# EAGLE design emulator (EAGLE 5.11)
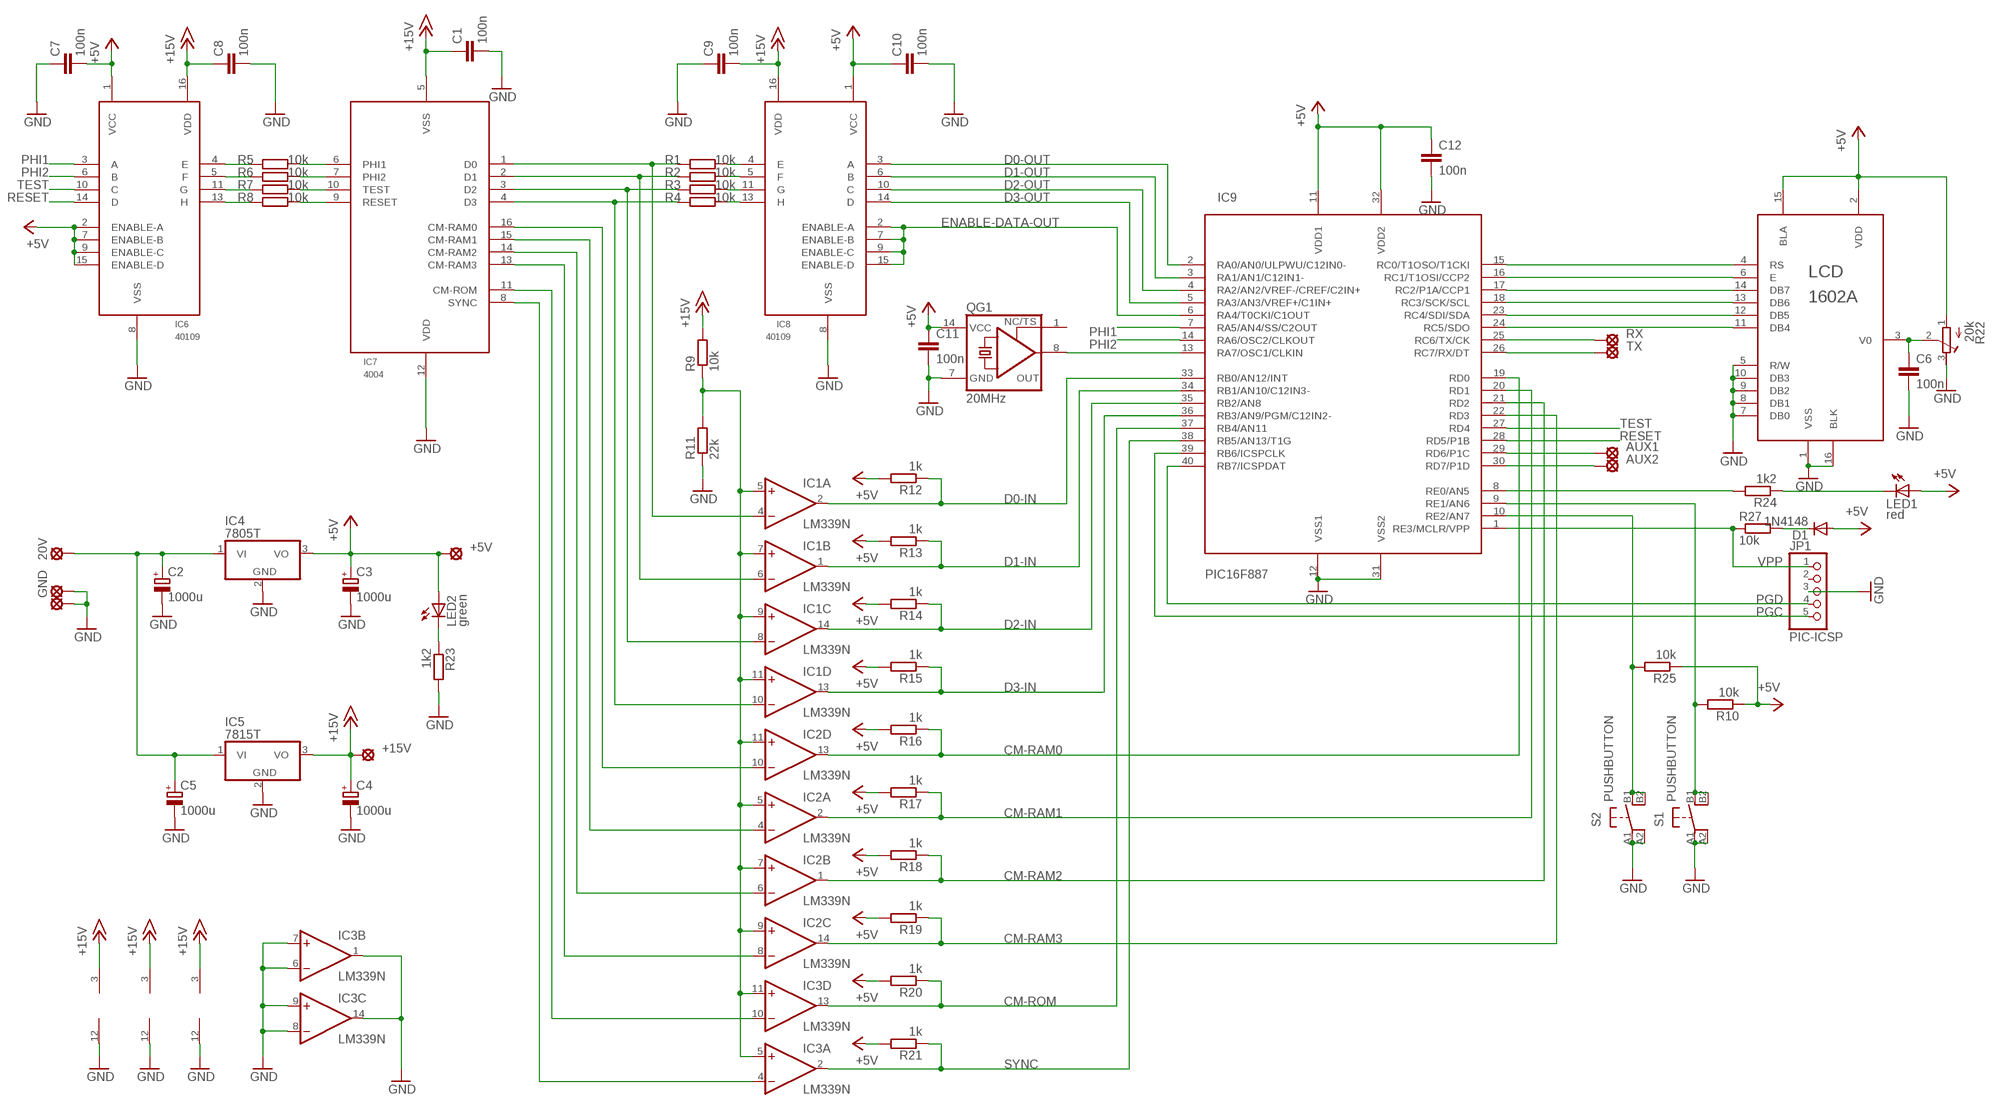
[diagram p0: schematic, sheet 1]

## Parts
20V  LSP10  [LSP10]
+5V  LSP10  [LSP10]
+15V  LSP10  [LSP10]
AUX1  LSP10  [LSP10]
AUX2  LSP10  [LSP10]
C1  100n  C-EU050-050X075  [C050-050X075]
C2  1000u  CPOL-EUE7.5-16  [E7,5-16]
C3  1000u  CPOL-EUE7.5-16  [E7,5-16]
C4  1000u  CPOL-EUE7.5-16  [E7,5-16]
C5  1000u  CPOL-EUE7.5-16  [E7,5-16]
C6  100n  C-EU050-050X075  [C050-050X075]
C7  100n  C-EU050-050X075  [C050-050X075]
C8  100n  C-EU050-050X075  [C050-050X075]
C9  100n  C-EU050-050X075  [C050-050X075]
C10  100n  C-EU050-050X075  [C050-050X075]
C11  100n  C-EU050-055X075  [C050-055X075]
C12  100n  C-EU050-050X075  [C050-050X075]
D1  1N4148  1N4148DO35-7  [DO35-7]
GND  LSP10  [LSP10]
GND29  LSP10  [LSP10]
IC1  LM339N  [DIL14]
IC2  LM339N  [DIL14]
IC3  LM339N  [DIL14]
IC4  7805T  [TO220H]
IC5  7815T  [TO220H]
IC6  40109  [DIL16]
IC7  4004  [DIL16/DIL40]
IC8  40109  [DIL16]
IC9  PIC16F887  [DIL40]
JP1  PIC-ICSP  PINHD-1X5  [1X05]
LCD  1602A  [1602A]
LED1  red  LED5MM  [LED5MM]
LED2  green  LED5MM  [LED5MM]
QG1  20MHz  XO-14  [DIL14S]
R1  10k  R-EU_0309/10  [0309/10]
R2  10k  R-EU_0309/10  [0309/10]
R3  10k  R-EU_0309/10  [0309/10]
R4  10k  R-EU_0309/10  [0309/10]
R5  10k  R-EU_0309/10  [0309/10]
R6  10k  R-EU_0309/10  [0309/10]
R7  10k  R-EU_0309/10  [0309/10]
R8  10k  R-EU_0309/10  [0309/10]
R9  10k  R-EU_0309/10  [0309/10]
R10  10k  R-EU_0309/10  [0309/10]
R11  22k  R-EU_0309/10  [0309/10]
R12  1k  R-EU_0309/10  [0309/10]
R13  1k  R-EU_0309/10  [0309/10]
R14  1k  R-EU_0309/10  [0309/10]
R15  1k  R-EU_0309/10  [0309/10]
R16  1k  R-EU_0309/10  [0309/10]
R17  1k  R-EU_0309/10  [0309/10]
R18  1k  R-EU_0309/10  [0309/10]
R19  1k  R-EU_0309/10  [0309/10]
R20  1k  R-EU_0309/10  [0309/10]
R21  1k  R-EU_0309/10  [0309/10]
R22  20k  R-TRIMM3339P  [RTRIM3339P]
R23  1k2  R-EU_0309/10  [0309/10]
R24  1k2  R-EU_0309/10  [0309/10]
R25  10k  R-EU_0309/10  [0309/10]
R27  10k  R-EU_0309/10  [0309/10]
RX  LSP10  [LSP10]
S1  PUSHBUTTON  [PUSHBUTTON]
S2  PUSHBUTTON  [PUSHBUTTON]
TX  LSP10  [LSP10]

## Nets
+5V: +5V.MP C3.+ C7.2 C10.1 C11.1 C12.1 D1.A IC4.3(VO) IC6.1(VCC) IC6.2(ENABLE-A) IC6.7(ENABLE-B) IC6.9(ENABLE-C) IC6.15(ENABLE-D) IC8.1(VCC) IC9.11(VDD1) IC9.32(VDD2) LCD.2(VDD) LCD.15(BLA) LED1.A LED2.A QG1.14(VCC) R10.1 R12.2 R13.2 R14.2 R15.2 R16.2 R17.2 R18.2 R19.2 R20.2 R21.2 R22.1(E) R25.1
+15V: +15V.MP C1.1 C4.+ C8.1 C9.2 IC1.3(P:V+) IC2.3(P:V+) IC3.3(P:V+) IC5.3(VO) IC6.16(VDD) IC7.5(VSS) IC8.16(VDD) R9.2
CM-RAM0: IC2.13(D:OUT) IC9.19(RD0) R16.1
CM-RAM1: IC2.2(A:OUT) IC9.20(RD1) R17.1
CM-RAM2: IC2.1(B:OUT) IC9.21(RD2) R18.1
CM-RAM3: IC2.14(C:OUT) IC9.22(RD3) R19.1
CM-ROM: IC3.13(D:OUT) IC9.37(RB4/AN11) R20.1
D0-IN: IC1.2(A:OUT) IC9.33(RB0/AN12/INT) R12.1
D0-OUT: IC8.3(A) IC9.2(RA0/AN0/ULPWU/C12IN0-)
D1-IN: IC1.1(B:OUT) IC9.34(RB1/AN10/C12IN3-) R13.1
D1-OUT: IC8.6(B) IC9.3(RA1/AN1/C12IN1-)
D2-IN: IC1.14(C:OUT) IC9.35(RB2/AN8) R14.1
D2-OUT: IC8.10(C) IC9.4(RA2/AN2/VREF-/CREF/C2IN+)
D3-IN: IC1.13(D:OUT) IC9.36(RB3/AN9/PGM/C12IN2-) R15.1
D3-OUT: IC8.14(D) IC9.5(RA3/AN3/VREF+/C1IN+)
ENABLE-DATA-OUT: IC8.2(ENABLE-A) IC8.7(ENABLE-B) IC8.9(ENABLE-C) IC8.15(ENABLE-D) IC9.6(RA4/T0CKI/C1OUT)
GND: C1.2 C2.- C3.- C4.- C5.- C6.2 C7.1 C8.2 C9.1 C10.2 C11.2 C12.2 GND29.MP GND.MP IC1.12(P:GND) IC2.12(P:GND) IC3.1(B:OUT) IC3.6(B:-IN) IC3.7(B:+IN) IC3.8(C:-IN) IC3.9(C:+IN) IC3.12(P:GND) IC3.14(C:OUT) IC4.2(GND) IC5.2(GND) IC6.8(VSS) IC7.12(VDD) IC8.8(VSS) IC9.12(VSS1) IC9.31(VSS2) JP1.3 LCD.1(VSS) LCD.5(R/W) LCD.7(DB0) LCD.8(DB1) LCD.9(DB2) LCD.10(DB3) LCD.16(BLK) QG1.7(GND) R11.1 R22.3(A) R23.2 S1.A1(P) S1.A2(P1) S2.A1(P) S2.A2(P1)
LCD-DB4: IC9.24(RC5/SDO) LCD.11(DB4)
LCD-DB5: IC9.23(RC4/SDI/SDA) LCD.12(DB5)
LCD-DB6: IC9.18(RC3/SCK/SCL) LCD.13(DB6)
LCD-DB7: IC9.17(RC2/P1A/CCP1) LCD.14(DB7)
LCD-E: IC9.16(RC1/T1OSI/CCP2) LCD.6(E)
LCD-RS: IC9.15(RC0/T1OSO/T1CKI) LCD.4(RS)
N$1: IC1.4(A:-IN) IC7.1(D0) R1.1
N$2: IC1.6(B:-IN) IC7.2(D1) R2.1
N$3: IC1.8(C:-IN) IC7.3(D2) R3.1
N$4: IC1.10(D:-IN) IC7.4(D3) R4.1
N$5: IC8.4(E) R1.2
N$6: IC8.5(F) R2.2
N$7: IC8.11(G) R3.2
N$8: IC8.13(H) R4.2
N$9: IC6.4(E) R5.1
N$10: IC6.5(F) R6.1
N$11: IC6.11(G) R7.1
N$12: IC6.13(H) R8.1
N$13: IC7.6(PHI1) R5.2
N$14: IC7.7(PHI2) R6.2
N$15: IC7.10(TEST) R7.2
N$16: IC7.9(RESET) R8.2
N$17: IC1.5(A:+IN) IC1.7(B:+IN) IC1.9(C:+IN) IC1.11(D:+IN) IC2.5(A:+IN) IC2.7(B:+IN) IC2.9(C:+IN) IC2.11(D:+IN) IC3.5(A:+IN) IC3.11(D:+IN) R9.1 R11.2
N$19: IC2.10(D:-IN) IC7.16(CM-RAM0)
N$20: IC2.4(A:-IN) IC7.15(CM-RAM1)
N$21: IC2.6(B:-IN) IC7.14(CM-RAM2)
N$22: IC2.8(C:-IN) IC7.13(CM-RAM3)
N$23: IC3.10(D:-IN) IC7.11(CM-ROM)
N$24: IC3.4(A:-IN) IC7.8(SYNC)
N$25: C6.1 LCD.3(V0) R22.2(S)
N$26: IC9.13(RA7/OSC1/CLKIN) QG1.8(OUT)
N$27: LED1.K(C) R24.1
N$28: 20V.MP C2.+ C5.+ IC4.1(VI) IC5.1(VI)
N$29: AUX1.MP IC9.29(RD6/P1C)
N$30: AUX2.MP IC9.30(RD7/P1D)
N$31: D1.C R27.2
N$32: IC9.9(RE1/AN6) R10.2 S1.B1(S) S1.B2(S1)
N$33: IC9.10(RE2/AN7) R25.2 S2.B1(S) S2.B2(S1)
N$34: LED2.K(C) R23.1
N$40: IC9.25(RC6/TX/CK) RX.MP
N$41: IC9.26(RC7/RX/DT) TX.MP
N$42: IC9.8(RE0/AN5) R24.2
PGC: IC9.39(RB6/ICSPCLK) JP1.5
PGD: IC9.40(RB7/ICSPDAT) JP1.4
PHI1: IC6.3(A) IC9.7(RA5/AN4/SS/C2OUT)
PHI2: IC6.6(B) IC9.14(RA6/OSC2/CLKOUT)
RESET: IC6.14(D) IC9.28(RD5/P1B)
SYNC: IC3.2(A:OUT) IC9.38(RB5/AN13/T1G) R21.1
TEST: IC6.10(C) IC9.27(RD4)
VPP: IC9.1(RE3/MCLR/VPP) JP1.1 R27.1
Unconnected: JP1.2 QG1.1(TS)

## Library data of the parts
20V +5V +15V AUX1 AUX2 GND GND29 RX TX = solpad:LSP10: SOLDER PAD
C1 C6-C12 = rcl:C-EU: CAPACITOR, European symbol
C2-C5 = rcl:CPOL-EU: POLARIZED CAPACITOR, European symbol
D1 = diode:1N4148: DIODE
IC1-IC3 = linear:LM339: Low Power Low Offset Voltage Quad Comparators with open collector; LM139/LM239/LM339/LM2901/LM3302
IC4 IC5 = linear:78*: Positive VOLTAGE REGULATOR Source: http://cache.national.com/ds/LM/LM78L05.pdf http://www.fairchildsemi.com/ds/LM/LM7805.pdf
IC6 IC8 = 4004:40109
IC7 = 4004:4004
IC9 = pic16f887:PIC16F887
JP1 = pinhead:PINHD-1X5: PIN HEADER
LCD = 1602A:1602A
LED1 LED2 = led:LED: LED
QG1 = crystal:XO-: CRYSTAL; OC_FARNELL: unknown; OC_NEWARK: unknown
R1-R21 R23-R25 R27 = rcl:R-EU_: RESISTOR, European symbol
R22 = rcl:R-TRIMM: Trimm resistor
S1 S2 = cartridge:PUSHBUTTON

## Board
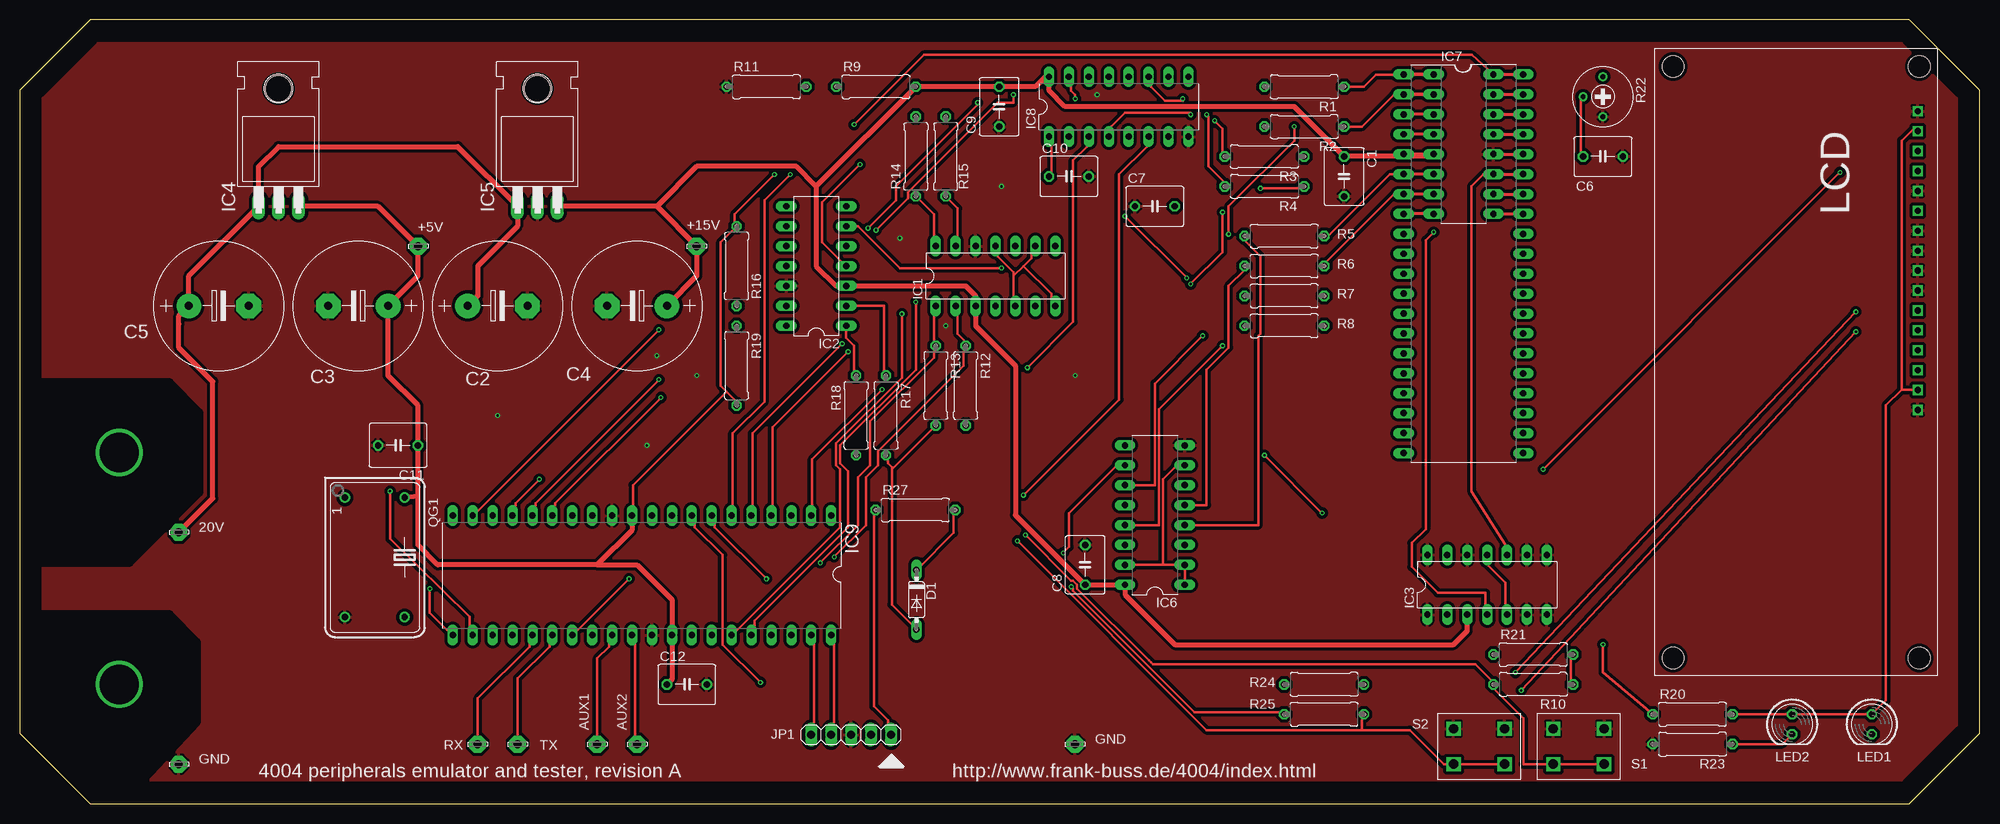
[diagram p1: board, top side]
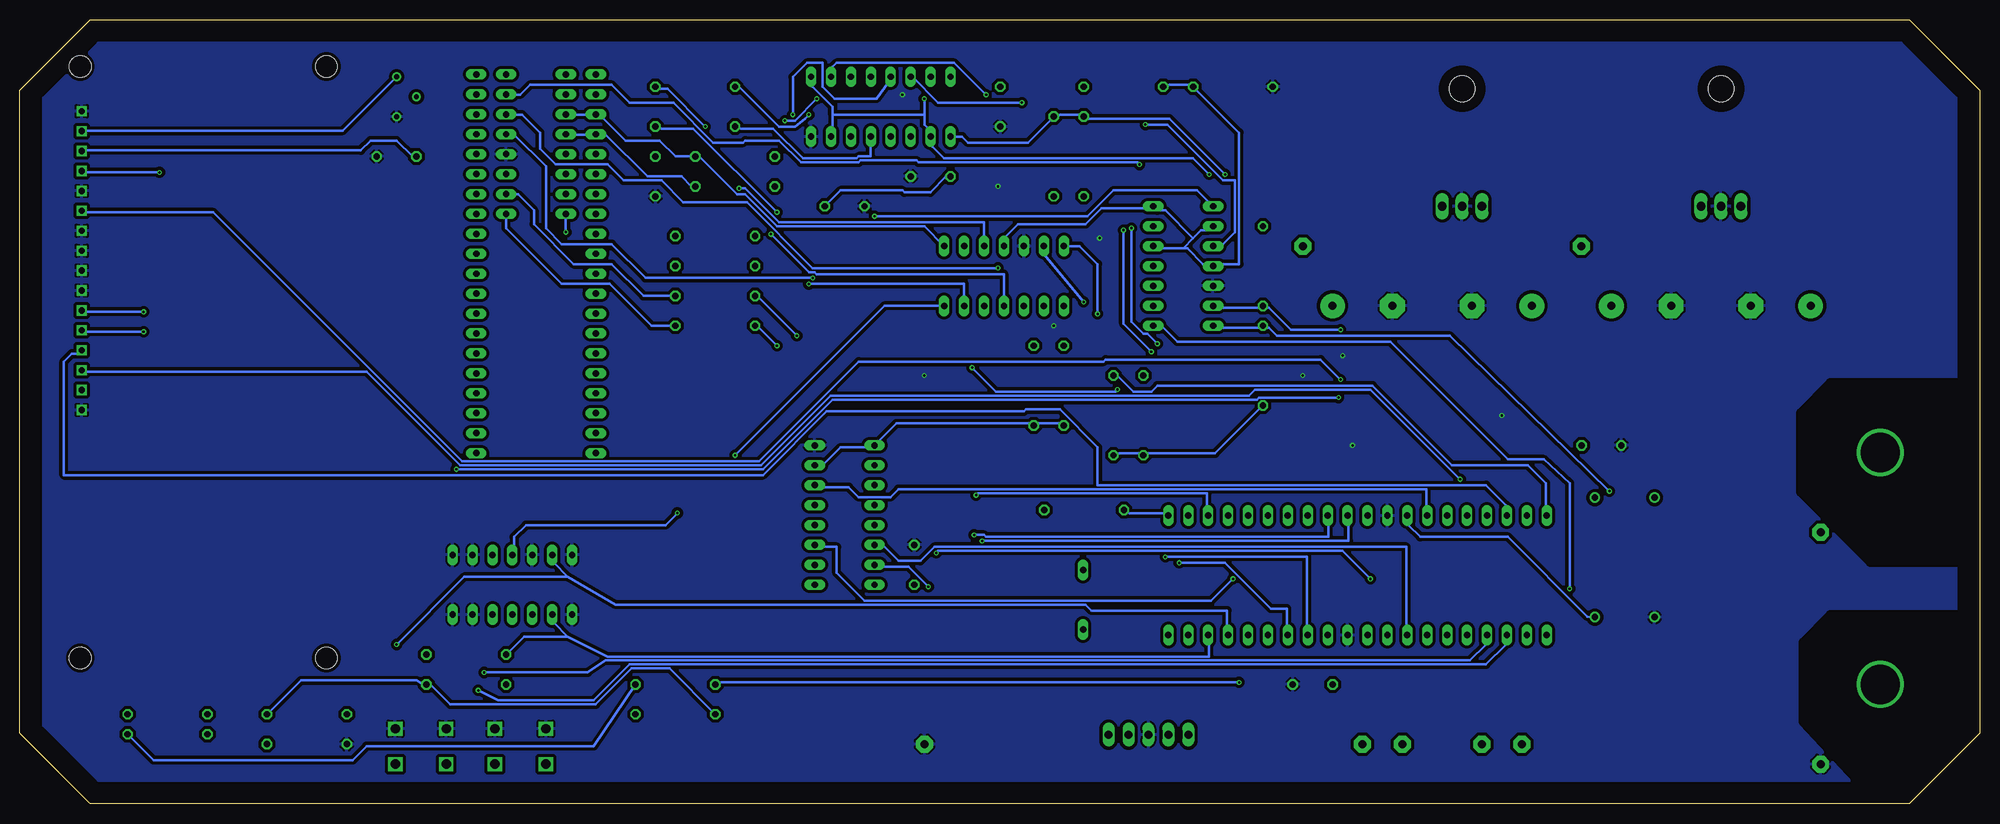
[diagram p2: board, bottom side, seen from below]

Size 250 x 100 mm. Coordinates in mm from the lower left corner, seen from the top.
Outline: 9,0 241,0 250,9 250,91 241,100 9,100 0,91 0,9 9,0
Copper layers (1*16): Top 0.035mm / dielectric 1.5mm / Bottom 0.035mm
Design rules "ITead_rule *": minimum track width 12mil, minimum drill 12mil, track to track 8mil, track to pad 8mil, pad to pad 8mil, via to via 8mil, smd to smd 0mil, copper to edge 10mil, drill to drill 10mil, minimum pad ring 10mil, minimum via ring 6mil, stop-mask expansion 2mil, vias tented up to drill 100mil, thermal gap 10mil
tRestrict: area 2.5,1.3 to 22.5,24.1; area 2.5,30.8 to 22.9,53.7
bRestrict: area 2.5,1.3 to 22.5,24.1; area 2.5,30.8 to 22.9,53.7

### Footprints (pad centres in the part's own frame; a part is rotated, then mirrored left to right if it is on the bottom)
LSP10 = drill 1.016 pad 2.159 octagon: MP 0,0
C050-050X075 = drill 0.813 octagon: 1 -2.54,0; 2 2.54,0
E7,5-16 = drill 1.016 pad 3.15 round: + -3.81,0 | drill 1.016 pad 3.15 octagon: - 3.81,0
C050-055X075 = drill 0.813 octagon: 1 -2.54,0; 2 2.54,0
DO35-7 = drill 0.813 long: A 3.81,0; C -3.81,0
DIL14 = drill 0.813 long: 1 -7.62,-3.81; 2 -5.08,-3.81; 3 -2.54,-3.81; 4 0,-3.81; 5 2.54,-3.81; 6 5.08,-3.81; 7 7.62,-3.81; 8 7.62,3.81; 9 5.08,3.81; 10 2.54,3.81; 11 0,3.81; 12 -2.54,3.81; 13 -5.08,3.81; 14 -7.62,3.81
TO220H = drill 1.118 long: 1 -2.54,-10.16; 2 0,-10.16; 3 2.54,-10.16 | hole 3.302: 0,4.826
DIL16 = drill 0.813 long: 1 -7.62,-3.81; 2 -5.08,-3.81; 3 -2.54,-3.81; 4 0,-3.81; 5 2.54,-3.81; 6 5.08,-3.81; 7 7.62,-3.81; 8 10.16,-3.81; 9 10.16,3.81; 10 7.62,3.81; 11 5.08,3.81; 12 2.54,3.81; 13 0,3.81; 14 -2.54,3.81; 15 -5.08,3.81; 16 -7.62,3.81
DIL16/DIL40 = drill 0.813 long: 1 -8.89,-3.81; 2 -6.35,-3.81; 3 -3.81,-3.81; 4 -1.27,-3.81; 5 1.27,-3.81; 6 3.81,-3.81; 7 6.35,-3.81; 8 8.89,-3.81; 9 8.89,3.81; 10 6.35,3.81; 11 3.81,3.81; 12 1.27,3.81; 13 -1.27,3.81; 14 -3.81,3.81; 15 -6.35,3.81; 16 -8.89,3.81; 17 -8.89,-7.62; 18 -6.35,-7.62; 19 6.35,-7.62; 20 8.89,-7.62; 21 -3.81,-7.62; 22 -1.27,-7.62; 23 3.81,-7.62; 24 1.27,-7.62; 25 11.43,-7.62; 26 13.97,-7.62; 27 16.51,-7.62; 28 19.05,-7.62; 29 21.59,-7.62; 30 24.13,-7.62; 31 26.67,-7.62; 32 29.21,-7.62; 33 31.75,-7.62; 34 34.29,-7.62; 35 36.83,-7.62; 36 39.37,-7.62; 37 39.37,7.62; 38 36.83,7.62; 39 34.29,7.62; 40 31.75,7.62; 41 29.21,7.62; 42 26.67,7.62; 43 24.13,7.62; 44 21.59,7.62; 45 19.05,7.62; 46 16.51,7.62; 47 13.97,7.62; 48 11.43,7.62; 49 8.89,7.62; 50 6.35,7.62; 51 3.81,7.62; 52 1.27,7.62; 53 -1.27,7.62; 54 -3.81,7.62; 55 -6.35,7.62; 56 -8.89,7.62
DIL40 = drill 0.813 long: 1 -24.13,-7.62; 2 -21.59,-7.62; 3 -19.05,-7.62; 4 -16.51,-7.62; 5 -13.97,-7.62; 6 -11.43,-7.62; 7 -8.89,-7.62; 8 -6.35,-7.62; 9 -3.81,-7.62; 10 -1.27,-7.62; 11 1.27,-7.62; 12 3.81,-7.62; 13 6.35,-7.62; 14 8.89,-7.62; 15 11.43,-7.62; 16 13.97,-7.62; 17 16.51,-7.62; 18 19.05,-7.62; 19 21.59,-7.62; 20 24.13,-7.62; 21 24.13,7.62; 22 21.59,7.62; 23 19.05,7.62; 24 16.51,7.62; 25 13.97,7.62; 26 11.43,7.62; 27 8.89,7.62; 28 6.35,7.62; 29 3.81,7.62; 30 1.27,7.62; 31 -1.27,7.62; 32 -3.81,7.62; 33 -6.35,7.62; 34 -8.89,7.62; 35 -11.43,7.62; 36 -13.97,7.62; 37 -16.51,7.62; 38 -19.05,7.62; 39 -21.59,7.62; 40 -24.13,7.62
1X05 = drill 1.016 long: 1 -5.08,0; 2 -2.54,0; 3 0,0; 4 2.54,0; 5 5.08,0
1602A = drill 0.8 square: 1 -31.15,14.29; 2 -28.61,14.29; 3 -26.07,14.29; 4 -23.53,14.29; 5 -20.99,14.29; 6 -18.45,14.29; 7 -15.91,14.29; 8 -13.37,14.29; 9 -10.83,14.29; 10 -8.29,14.29; 11 -5.75,14.29; 12 -3.21,14.29; 13 -0.67,14.29; 14 1.87,14.29; 15 4.41,14.29; 16 6.95,14.29 | hole 2.8: -36.85,14.49; 38.55,14.49; 38.55,-16.91; -36.85,-16.91
LED5MM = drill 0.813 octagon: A -1.27,0; K 1.27,0
DIL14S = drill 0.813 round: 1 -7.62,-3.81; 7 7.62,-3.81; 8 7.62,3.81; 14 -7.62,3.81
0309/10 = drill 0.813 octagon: 1 -5.08,0; 2 5.08,0
RTRIM3339P = drill 0.61 round: 1 -2.54,0; 2 0,-2.54; 3 2.54,0
PUSHBUTTON = drill 1.2 square: A1 0,4.5; A2 6.5,4.5; B1 0,0; B2 6.5,0

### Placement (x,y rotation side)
20V  20.32,34.64 0 top
+5V  50.8,71.12 0 top
+15V  86.36,71.12 0 top
AUX1  73.66,7.62 0 top
AUX2  78.74,7.62 0 top
C1  168.91,80.01 270 top
C2  60.96,63.5 0 top
C3  43.18,63.5 180 top
C4  78.74,63.5 180 top
C5  25.4,63.5 0 top
C6  201.93,82.55 0 top
C7  144.78,76.2 0 top
C8  135.89,30.48 90 top
C9  124.93,88.9 90 top
C10  133.82,80.01 0 top
C11  48.26,45.72 180 top
C12  85.09,15.24 0 top
D1  114.36,26.03 270 top
GND  20.32,5.08 0 top
GND29  134.62,7.62 0 top
IC1  124.46,67.31 0 top
IC2  101.6,68.58 90 top
IC3  187.16,27.94 0 top
IC4  33.02,86.36 0 top
IC5  66.04,86.36 0 top
IC6  144.78,35.56 90 top
IC7  184.15,84.11 270 top
IC8  138.9,88.9 0 top
IC9  79.37,29.15 180 top
JP1  106.04,8.83 180 top
LCD  227.78,57.17 270 top
LED1  236.22,10.16 270 top
LED2  226.06,10.16 270 top
QG1  45.3,31.43 270 top
R1  163.83,91.44 180 top
R2  163.83,86.36 180 top
R3  158.75,82.55 180 top
R4  158.75,78.74 180 top
R5  161.29,72.39 0 top
R6  161.29,68.58 0 top
R7  161.29,64.77 0 top
R8  161.29,60.96 0 top
R9  109.22,91.44 0 top
R10  193.04,15.24 180 top
R11  95.25,91.44 0 top
R12  120.65,53.34 270 top
R13  116.84,53.34 270 top
R14  114.3,82.55 90 top
R15  118.11,82.55 90 top
R16  91.44,68.58 90 top
R17  110.49,49.53 270 top
R18  106.68,49.53 270 top
R19  91.44,55.88 270 top
R20  213.36,11.43 0 top
R21  193.04,19.05 0 top
R22  201.93,90.17 270 top
R23  213.36,7.62 180 top
R24  166.37,15.24 180 top
R25  166.37,11.43 0 top
R27  114.24,37.47 0 top
RX  58.42,7.62 0 top
S1  195.58,5.08 0 top
S2  182.88,5.08 0 top
TX  63.5,7.62 0 top

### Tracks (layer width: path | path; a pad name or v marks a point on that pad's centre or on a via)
+5V  (via drill 0.3)
  Top 0.305: C10.1 131.32,80.01 131.57,80.26 131.57,84.84 131.32,85.09 IC8.1 | 145.8,30.48 IC6.2 IC6.1 | IC6.15 145.8,30.48 | 145.8,30.48 145.8,41.4 147.57,43.18 IC6.7 | 111.25,42.67 111.25,42.93 110.74,43.43 110.74,43.69 110.49,43.94 R17.2 | 111.25,42.67 111.25,25.4 114.3,22.35 D1.A | 91.19,73.41 89.41,71.63 89.41,53.34 90.17,52.58 | 90.17,52.58 91.44,51.31 R19.2 | R13.2 111.25,42.67 | v96.27,80.26 91.19,75.18 91.19,73.41 | 91.19,73.41 R16.2 | 90.17,52.58 78.23,40.64 78.23,36.83 IC9.11 | 240.03,52.83 242.06,52.83 LCD.15 | 240.03,52.83 240.03,84.58 241.55,86.11 242.06,86.11 242.06,85.85 LCD.2 | R21.2 197.87,18.8 197.87,15.49 R10.1 | 240.03,52.83 238,50.8 238,13.21 LED1.A LED2.A R20.2 | v134.11,27.69 134.37,27.43 134.37,27.18 149.86,11.68 161.29,11.68 R25.1
  Top 0.61: IC4.3 45.72,76.2 +5V.MP 50.8,67.31 C3.+ 46.99,54.61 50.8,50.8 C11.1 50.8,39.22 | 50.8,39.22 QG1.14 | 50.8,39.22 50.8,33.02 53.34,30.48 73.66,30.48 | IC9.11 78.1,34.92 73.66,30.48 | 73.66,30.48 78.74,30.48 83.18,26.04 IC9.32 83.18,15.87 C12.1
  Bottom 0.305: C7.2 145.29,78.23 137.41,78.23 137.16,77.98 133.86,77.98 131.83,80.01 C10.1 | IC8.1 129.79,85.09 129.03,84.33 121.41,84.33 R15.2 117.6,87.63 117.35,87.88 114.55,87.88 R14.2 114.05,87.38 103.38,87.38 v96.27,80.26 | IC6.7 147.57,43.18 145.29,45.47 141.22,45.47 IC6.9 138.18,48.51 119.89,48.51 | R13.2 117.09,48.51 119.89,48.51 | 119.89,48.51 120.14,48.26 R12.2 | 106.93,44.7 109.73,44.7 109.98,44.45 R17.2 | R19.2 97.54,44.7 106.93,44.7 | 106.93,44.7 R18.2 | R22.1 208.79,85.85 242.06,85.85 LCD.2 | R25.1 167.13,17.27 171.96,17.27 176.53,12.7 195.07,12.7 197.61,15.24 R10.1 198.63,15.24 199.39,15.75 214.12,15.75 R20.2 | IC6.15 140.72,30.23 136.65,30.23 v134.11,27.69
+15V
  Top 0.61: 81.28,76.2 IC5.3 | 81.28,76.2 +15V.MP 86.36,67.31 C4.+ | 101.6,78.74 101.6,68.58 104.14,66.04 IC2.3 120.65,66.04 121.92,64.77 IC1.3 121.92,60.96 127,55.88 127,36.83 C8.1 IC6.16 140.97,26.67 147.32,20.32 182.88,20.32 184.62,22.06 IC3.3 184.62,24.6 | 101.6,78.74 99.06,81.28 86.36,81.28 81.28,76.2 | 101.6,78.74 R9.2 C9.2 129.54,91.44 130.81,92.71 IC8.16 131.28,90.97 133.35,88.9 162.56,88.9 C1.1 180.05,82.55 IC7.5
CM-RAM0  (via drill 0.3)
  Top 0.305: v81.53,60.45 57.91,36.83 IC9.19
  Bottom 0.305: v81.53,60.45 87.88,60.45 90.68,63.25 | 90.68,63.25 90.93,63.5 R16.1 | IC2.13 97.54,63.25 90.68,63.25
CM-RAM1
  Top 0.305: IC2.2 110.24,63.5 110.24,54.86 R17.1
  Bottom 0.305: R17.1 109.98,54.61 107.95,52.58 105.66,52.58 104.9,53.34 77.47,53.34 67.31,43.18 57.66,43.18 55.37,40.89 55.37,36.83 IC9.20
CM-RAM2  (via drill 0.3)
  Top 0.305: v52.32,27.43 52.32,24.38 55.12,21.59 IC9.21 | R18.1 106.43,54.86 106.43,58.42 105.41,59.44 IC2.1
  Bottom 0.305: v52.32,27.43 52.32,40.89 55.63,43.94 60.2,43.94 75.18,58.93 102.36,58.93 104.39,60.96 IC2.1
CM-RAM3  (via drill 0.3)
  Top 0.305: v47.24,39.88 47.24,33.78 57.4,23.88 57.4,21.84 57.66,21.59 IC9.22
  Bottom 0.305: v47.24,39.88 67.56,59.69 89.66,59.69 90.68,60.71 | 90.68,60.71 90.93,60.96 R19.1 | IC2.14 97.54,60.71 90.68,60.71
CM-ROM  (via drill 0.3)
  Top 0.305: R20.1 201.93,16.76 v201.93,20.32
  Bottom 0.305: 180.09,28.96 181.86,30.73 181.86,31.75 IC3.13 | 180.09,28.96 173.99,25.4 114.05,25.4 113.28,24.64 96.01,24.64 96.01,21.59 IC9.37 | v201.93,20.32 193.29,28.96 180.09,28.96
D0-IN  (via drill 0.3)
  Top 0.305: v103.89,31.5 107.95,35.56 107.95,41.66 109.47,43.18 109.47,44.96 120.4,55.88 120.4,57.66 120.65,57.91 R12.1 120.65,58.93 119.63,59.94 119.63,63.25 IC1.2
  Bottom 0.305: v103.89,31.5 85.85,31.5 85.85,21.59 IC9.33
D0-OUT  (via drill 0.3)
  Top 0.305: v109.98,52.83 101.09,43.94 101.09,36.83 IC9.2 | v128.52,55.63 134.37,61.47 134.37,82.04 136.14,83.82 136.14,85.09 IC8.3
  Bottom 0.305: v109.98,52.83 110.24,52.58 125.48,52.58 v128.52,55.63
D1-IN  (via drill 0.3)
  Top 0.305: v102.11,30.73 106.93,35.56 106.93,41.66 108.46,43.18 108.46,48.77 116.59,56.9 116.59,57.66 | 116.59,57.66 116.84,57.91 R13.1 | IC1.1 116.59,63.25 116.59,57.66
  Bottom 0.305: v102.11,30.73 96.27,30.73 90.42,24.89 88.39,24.89 88.39,21.59 IC9.34
D1-OUT  (via drill 0.3)
  Top 0.305: v128.02,39.37 140.21,51.56 140.21,80.26 143.76,83.82 143.76,85.09 IC8.6
  Bottom 0.305: v128.02,39.37 127.76,39.62 98.55,39.62 98.55,36.83 IC9.3
D2-IN  (via drill 0.3)
  Top 0.305: v112.52,62.48 112.52,54.36 104.14,45.97 104.14,43.18 104.65,42.67 104.65,35.31 90.93,21.59 IC9.35 | R14.1 116.59,75.18 116.59,71.37 IC1.14
  Bottom 0.305: v112.52,62.48 112.52,68.83 114.81,71.12 IC1.14
D2-OUT  (via drill 0.3)
  Top 0.305: v105.66,57.66 96.01,48.01 96.01,36.83 IC9.4 | v109.22,73.15 113.28,77.22 113.28,77.98 124.71,89.41 126.75,89.41 v126.75,90.42
  Bottom 0.305: v105.66,57.66 109.22,61.21 v109.22,73.15 | v126.75,90.42 130.81,94.49 145.8,94.49 146.3,93.98 146.3,92.71 IC8.10
D3-IN  (via drill 0.3)
  Top 0.305: v114.3,64.01 114.3,55.37 104.65,45.72 104.65,43.43 105.66,42.42 105.66,35.31 93.73,23.37 93.73,21.84 93.47,21.59 IC9.36 | R15.1 119.63,75.95 119.63,71.37 IC1.13
  Bottom 0.305: v114.3,64.01 119.38,70.1 IC1.13
D3-OUT  (via drill 0.3)
  Top 0.305: v104.9,58.67 93.47,47.24 93.47,36.83 IC9.5 | v108.2,73.41 111.76,76.96 111.76,78.74 122.17,89.15 v122.17,89.41
  Bottom 0.305: v104.9,58.67 106.17,59.94 106.68,59.94 108.2,61.47 v108.2,73.41 | v122.17,89.41 132.84,89.41 136.14,92.71 IC8.14
ENABLE-DATA-OUT  (via drill 0.3)
  Top 0.305: v98.3,80.26 95,76.96 95,51.31 90.93,47.24 90.93,36.83 IC9.6 | v134.62,89.92 134.62,90.42 134.11,90.93 134.11,92.46 133.86,92.71 IC8.15
  Bottom 0.305: 146.3,87.88 146.3,88.9 148.84,91.44 148.84,92.71 IC8.9 | 146.3,87.88 146.3,85.09 IC8.7 | v98.3,80.26 100.33,82.3 132.08,82.3 133.6,83.82 133.6,85.09 IC8.2 133.86,85.09 133.86,85.85 134.62,86.61 134.62,87.88 | 134.62,87.88 v134.62,89.92 | 134.62,87.88 146.3,87.88
GND  (via drill 0.3)
  other vias: 60.96,49.53 81.28,57.15 86.36,54.61 80.01,45.72 134.62,54.61 118.11,60.96 112.27,72.14 125.22,78.74 137.41,90.42
  pour Bottom (isolate 0.406): 3,90 10,97 240,97 247,90 247,10 240,3 10,3 3,10
  pour Top (isolate 0.406): 10,97 240,97 247,90 247,10 240,3 10,3 3,10 3,90
LCD-DB4  (via drill 0.3)
  Top 0.305: v234.19,62.74 v190.75,16.76
  Bottom 0.305: v234.19,62.74 242.06,62.74 LCD.11 | v190.75,16.76 177.55,16.76 175.26,18.29 65.02,18.29 62.99,20.32 62.99,21.34 IC9.24
LCD-DB5  (via drill 0.3)
  Top 0.305: v234.19,60.2 v191.52,14.48
  Bottom 0.305: v234.19,60.2 242.06,60.2 LCD.12 | v191.52,14.48 188.98,13.21 176.78,13.21 172.21,17.78 62.99,17.78 60.45,20.32 60.45,21.34 IC9.23
LCD-DB6
  Bottom 0.305: LCD.13 242.32,57.66 242.57,57.4 243.33,57.4 244.35,56.39 244.35,41.91 155.19,41.91 147.07,50.04 121.92,50.04 121.67,50.29 117.35,50.29 112.52,45.47 112.52,40.64 62.99,40.64 60.45,38.1 60.45,36.83 IC9.18
LCD-DB7  (via drill 0.3)
  Top 0.305: v66.29,41.4 63.25,38.35 63.25,38.1 62.99,37.85 62.99,36.83 IC9.17
  Bottom 0.305: v66.29,41.4 77.72,52.83 92.46,52.83 93.22,52.07 146.56,52.07 155.45,43.18 193.8,43.18 205.74,55.12 242.06,55.12 LCD.14
LCD-E  (via drill 0.3)
  Top 0.305: v81.53,54.1 65.79,38.35 65.79,38.1 65.53,37.85 65.53,36.83 IC9.16
  Bottom 0.305: v81.53,54.1 84.07,56.64 111.51,56.64 111.76,56.39 143,56.39 155.7,43.69 193.55,43.69 225.3,75.44 242.06,75.44 LCD.6
LCD-RS  (via drill 0.3)
  Top 0.305: v232.16,80.52 v194.31,42.67 | v81.79,51.82 68.33,38.35 68.33,38.1 68.07,37.85 68.07,36.83 IC9.15
  Bottom 0.305: v232.16,80.52 242.06,80.52 LCD.4 | v194.31,42.67 155.19,42.67 146.3,51.56 92.2,51.56 91.95,51.82 v81.79,51.82
N$1  (via drill 0.3)
  Top 0.305: v154.18,72.64 154.18,76.2 162.56,84.58 v162.56,86.36 | R1.1 171.45,91.44 172.97,92.96 180.3,92.96 IC7.1
  Bottom 0.305: IC1.4 124.46,67.56 148.34,67.56 148.59,67.82 149.35,67.82 v154.18,72.64 | v162.56,86.36 167.39,91.19 168.66,91.19 R1.1
N$2  (via drill 0.3)
  Top 0.305: v149.35,66.29 153.42,70.36 v153.42,75.44 | IC7.2 180.3,90.42 175.26,90.42 171.2,86.36 R2.1
  Bottom 0.305: IC1.6 129.54,66.29 v149.35,66.29 | v153.42,75.44 164.08,86.11 168.15,86.11 168.4,86.36 R2.1 | IC7.2 180.34,90.42
N$3
  Bottom 0.305: IC1.8 134.62,73.66 153.42,73.66 157.48,77.72 158.5,77.72 163.32,82.55 R3.1 166.37,82.55 168.4,84.58 172.72,84.58 176.02,87.88 180.3,87.88 IC7.3 180.34,87.88
N$4  (via drill 0.3)
  Top 0.305: v158.24,78.49 163.83,78.49 R4.1
  Bottom 0.305: IC1.10 127,74.17 153.16,74.17 157.48,78.49 v158.24,78.49 | R4.1 164.34,78.74 165.61,80.01 169.93,80.01 175.26,85.34 180.3,85.34 IC7.4 180.34,85.34
N$5  (via drill 0.3)
  Top 0.305: v149.35,87.88 149.35,88.14 140.97,88.14 139.19,86.36 139.19,85.34 138.94,85.09 IC8.4
  Bottom 0.305: v149.35,87.88 149.86,87.38 151.13,86.36 153.16,86.36 158.24,91.44 R1.2
N$6
  Bottom 0.305: R2.2 158.24,86.36 157.99,86.11 153.92,86.11 150.11,82.3 143.26,82.3 143,82.55 141.48,82.55 141.48,85.09 IC8.5
N$7  (via drill 0.3)
  Top 0.305: v148.34,89.92 148.34,89.66 146.05,89.66 144.27,91.44 144.27,92.46 144.02,92.71 IC8.11 | v152.4,87.12 153.42,86.11 153.42,82.8 R3.2
  Bottom 0.305: v148.34,89.92 151.13,87.12 v152.4,87.12
N$8  (via drill 0.3)
  Top 0.305: v151.38,87.88 151.64,87.63 151.64,81.28 153.67,79.25 R4.2
  Bottom 0.305: v151.38,87.88 151.38,92.71 149.61,94.49 147.57,94.49 147.57,91.44 146.05,89.92 140.72,89.92 138.68,92.71 IC8.13
N$9
  Top 0.305: IC6.4 157.99,35.56 157.99,59.69 158.24,59.94 158.24,69.85 156.21,71.88 R5.1
N$10
  Top 0.305: IC6.5 151.38,38.1 151.38,55.37 154.18,58.17 154.18,66.04 156.21,68.07 R6.1
N$11  (via drill 0.3)
  Top 0.305: IC6.11 144.78,40.64 144.78,53.59 v150.88,59.69
  Bottom 0.305: v150.88,59.69 155.96,64.77 R7.1
N$12  (via drill 0.3)
  Top 0.305: IC6.13 145.29,35.56 145.29,50.29 v153.42,58.42
  Bottom 0.305: v153.42,58.42 155.96,60.96 R8.1
N$13
  Top 0.305: R5.2 166.88,72.39 174.75,80.26 180.3,80.26 IC7.6
N$14
  Top 0.305: R6.2 166.37,68.83 175.26,77.72 180.3,77.72 IC7.7
N$15
  Bottom 0.305: R7.2 170.43,64.77 174.5,68.83 179.32,68.83 184.4,73.91 184.4,75.69 186.44,77.72 187.92,77.72 IC7.10
N$16
  Bottom 0.305: R8.2 169.42,60.96 174.75,66.29 180.85,66.29 187.96,73.41 IC7.9
N$17  (via drill 0.3)
  Top 0.305: IC3.5 189.48,24.13 189.48,28.19 186.94,30.73 186.94,31.75 IC3.11 | IC1.11 124.71,70.87 124.71,69.85 126.75,67.82 126.75,67.31 | 126.75,67.31 126.75,63.75 IC1.5 | IC1.9 129.03,70.61 129.03,69.6 128.02,68.58 | 126.75,67.31 128.02,68.58 | IC1.7 131.57,64.01 131.57,65.02 128.02,68.58 | v158.75,44.45 v166.12,37.08
  Bottom 0.305: R9.1 103.63,91.44 103.38,91.69 100.58,91.69 R11.2 94.49,85.6 94.49,68.83 98.04,68.83 | 98.04,68.83 99.06,68.83 101.09,70.87 101.6,70.87 | 101.6,70.87 105.16,70.87 IC2.5 | IC2.9 98.3,73.15 99.31,73.15 100.33,72.14 | 101.6,70.87 100.33,72.14 | 100.33,72.14 103.89,75.69 104.9,75.69 IC2.7 105.66,75.95 112.01,75.95 114.05,73.91 122.68,73.91 124.46,72.14 IC1.11 | 98.04,68.83 IC2.11 | v158.75,44.45 139.7,63.5 IC1.7 | IC3.11 186.94,31.75 186.94,34.04 185.42,35.56 167.64,35.56 v166.12,37.08
N$18  (via drill 5)
  other vias: 12.7,15.24
N$19  (via drill 0.3)
  Top 0.305: v106.43,86.61 115.32,95.5 185.2,95.5 IC7.16
  Bottom 0.305: IC2.10 97.54,71.37 96.52,71.37 95,72.9 95,79.5 96.52,79.5 103.63,86.61 v106.43,86.61
N$20  (via drill 0.3)
  Top 0.305: IC2.4 102.36,71.63 102.36,76.71 v107.19,81.53
  Bottom 0.305: v107.19,81.53 107.44,81.79 135.38,81.79 135.64,82.04 142.75,82.04 143,81.79 150.37,81.79 153.16,84.58 157.48,84.58 157.73,84.33 161.54,84.33 166.62,89.41 172.21,89.41 174.5,91.69 184.91,91.69 186.18,90.42 187.92,90.42 IC7.15
N$21  (via drill 0.3)
  Top 0.305: IC2.6 106.93,73.66 112.27,68.33 v125.22,68.33
  Bottom 0.305: v125.22,68.33 148.84,68.33 157.23,76.71 165.35,76.71 168.15,79.5 172.97,79.5 175.01,81.53 181.61,81.53 183.64,83.57 183.64,85.6 185.93,87.88 187.92,87.88 IC7.14 187.96,87.88
N$22  (via drill 0.3)
  Top 0.305: v148.84,67.06 v140.97,74.93
  Bottom 0.305: IC2.8 99.82,78.23 110.49,78.23 113.79,74.93 v140.97,74.93 | 187.96,85.34 IC7.13 187.92,85.34 186.94,85.34 182.88,81.28 182.88,73.41 180.85,71.37 174.5,71.37 170.18,67.06 v148.84,67.06
N$23
  Top 0.305: IC3.10 189.48,31.75 189.48,33.02 185.17,39.88 185.17,78.74 186.69,80.26 187.92,80.26 IC7.11
  Bottom 0.305: IC7.11 187.96,80.26
N$24  (via drill 0.3)
  Top 0.305: v180.34,72.9 179.32,71.88 179.32,35.05 177.55,33.27 177.55,30.23 180.85,26.92 186.94,26.92 186.94,24.13 IC3.4
  Bottom 0.305: IC7.8 v180.34,72.9
N$25
  Top 0.305: R22.2 199.14,89.92 199.14,82.8 C6.1
  Bottom 0.305: C6.1 199.9,82.55 201.93,84.58 205.23,84.58 206.5,83.31 242.06,83.31 LCD.3
N$26
  Bottom 0.305: QG1.8 50.04,23.88 60.2,34.04 71.37,34.04 72.9,35.56 72.9,36.58 IC9.13
N$27
  Bottom 0.305: R24.1 176.78,7.37 205.74,7.37 207.52,5.59 232.92,5.59 LED1.K
N$28
  Top 0.61: C2.+ 58.42,64.77 58.42,68.58 63.5,73.66 IC5.1 55.88,83.82 33.02,83.82 30.48,81.28 IC4.1 21.59,67.31 C5.+ 20.32,62.23 20.32,61.21 20.32,58.17 24.64,53.85 24.64,38.96 20V.MP
N$29
  Top 0.305: AUX1.MP 73.66,18.54 75.18,20.07 75.18,21.08 75.44,21.34 IC9.29
N$30
  Top 0.305: AUX2.MP 78.49,7.87 78.49,21.08 78.23,21.34 IC9.30
N$31
  Top 0.305: D1.C 114.55,29.97 119.13,34.54 119.13,37.34 R27.2
N$32  (via drill 0.3)
  Top 0.305: S1.B2 S1.B1 191.77,5.08 191.77,10.92 187.96,14.73 R10.2 187.96,15.49 185.67,17.78 144.53,17.78 144.27,18.03 144.02,18.29 134.87,27.43 134.87,27.94 134.37,28.45 134.11,28.45 v128.27,34.29
  Bottom 0.305: v128.27,34.29 127,34.29 126.75,34.04 83.06,34.04 83.06,36.58 IC9.9
N$33  (via drill 0.3)
  Top 0.305: S2.B2 S2.B1 181.61,5.08 177.29,9.4 171.2,9.4 | v127.25,33.53 151.38,9.4 171.2,9.4 | 171.2,9.4 171.2,10.67 171.45,10.92 R25.2
  Bottom 0.305: v127.25,33.53 80.52,33.53 80.52,36.58 IC9.10
N$34
  Top 0.305: R23.1 224.79,7.62 LED2.K
N$35  (via drill 5)
  other vias: 12.7,44.8
N$40
  Top 0.305: RX.MP 58.42,13.46 65.02,20.07 65.02,21.08 65.28,21.34 IC9.25
N$41
  Top 0.305: TX.MP 63.5,16 67.56,20.07 67.56,21.08 67.82,21.34 IC9.26
N$42  (via drill 0.3)
  Top 0.305: v94.49,15.49 89.66,20.32 89.66,31.75 86.11,35.31 86.11,36.32 85.85,36.58 IC9.8
  Bottom 0.305: v94.49,15.49 160.53,15.49 160.78,15.24 R24.2
PGC
  Top 0.305: IC9.39 101.09,21.34 101.35,21.08 101.35,10.41 101.09,10.16 101.09,8.89 JP1.5
PGD
  Top 0.305: IC9.40 103.63,21.34 103.89,21.08 103.89,10.41 103.63,10.16 103.63,8.89 JP1.4
PHI1  (via drill 0.3)
  Top 0.305: v95.25,28.7 88.65,35.31 88.65,36.32 88.39,36.58 IC9.7
  Bottom 0.305: v95.25,28.7 98.04,25.91 142.24,25.91 145.8,29.46 145.8,32.77 148.34,32.77 IC6.3
PHI2
  Bottom 0.305: IC6.6 148.34,40.39 144.27,40.39 143,39.12 138.94,39.12 137.92,40.13 70.61,40.13 70.61,36.83 IC9.14
RESET
  Bottom 0.305: IC6.14 139.95,33.02 137.92,30.99 135.13,30.99 133.35,32.77 73.15,32.77 73.15,21.59 IC9.28
SYNC
  Bottom 0.305: 180.09,21.34 181.86,23.11 181.86,24.13 IC3.2 | 180.09,21.34 175.01,18.8 98.3,18.8 98.3,21.34 IC9.38 | R21.1 185.67,21.34 180.09,21.34
TEST  (via drill 0.3)
  Top 0.305: v77.72,28.7 70.61,21.59 IC9.27 | v133.1,32 133.86,32.77 133.86,37.08 139.95,43.18 IC6.10
  Bottom 0.305: v77.72,28.7 81.28,32.26 132.84,32.26 v133.1,32
VPP
  Top 0.305: JP1.1 111,8.89 110.74,9.14 110.74,10.67 108.97,12.45 108.97,37.34 R27.1
  Bottom 0.305: IC9.1 103.63,36.83 103.89,37.08 108.46,37.08 108.71,37.34 108.97,37.34 R27.1

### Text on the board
tNames: GND | 4004 peripherals emulator and tester, revision A | http://www.frank-buss.de/4004/index.html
